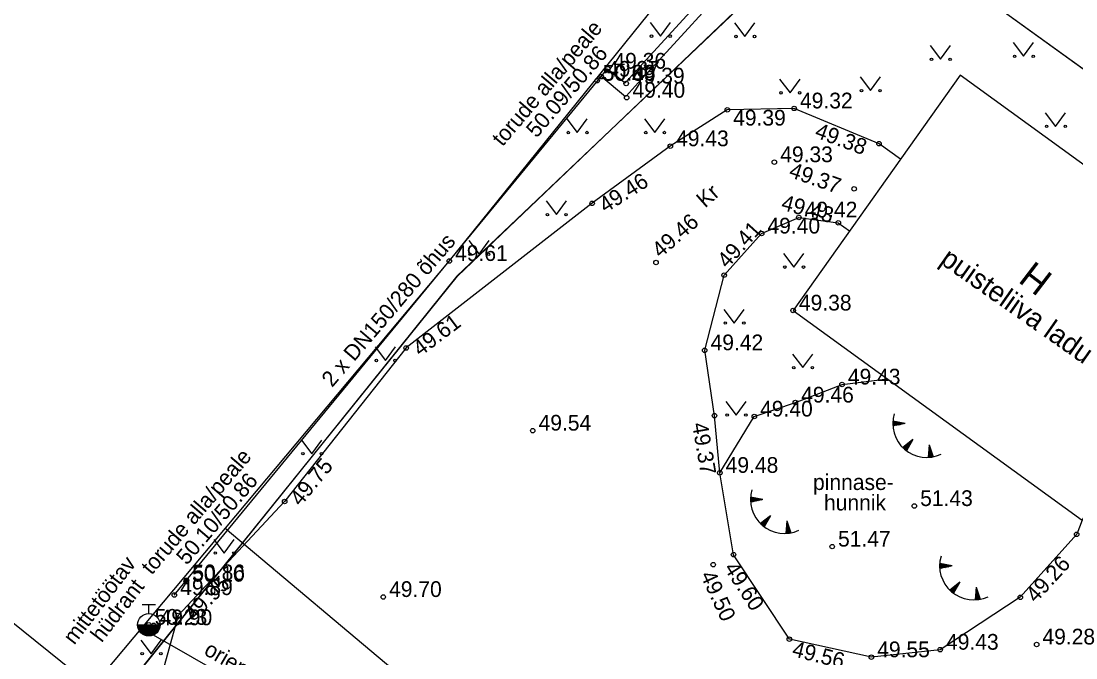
# Model space of a CAD drawing. Extents: x 640876 to 641418, y 6455595 to 6456085.
# Drawn here: x 641120.09 to 641167.04, y 6455852.02 to 6455880.34 of the extents above; entities that cross this region are included whole.
import ezdxf

# ---------------------------------------------------------------- set-up
doc = ezdxf.new("R2010")
doc.units = 0
for name, color, linetype in [('ABIJOONIS', 7, 'Continuous'), ('HALJASTUS', 7, 'Continuous'), ('HOONE', 7, 'Continuous'), ('HOONEDET', 7, 'Continuous'), ('KORGUS', 7, 'Continuous'), ('KTRASS', 7, 'Continuous'), ('MOOTKORG', 7, 'Continuous'), ('MOOTMPUNKT', 7, 'Continuous'), ('PIIR', 7, 'Continuous'), ('RELJEEF', 7, 'Continuous'), ('TEE', 7, 'Continuous'), ('TTRASS', 7, 'Continuous'), ('VKAEV', 7, 'Continuous'), ('VTRASS', 7, 'Continuous')]:
    doc.layers.add(name, color=color, linetype=linetype)

msp = doc.modelspace()

# ---------------------------------------------------------------- linework, layer by layer
at = {"layer": 'HALJASTUS'}
for p, q in [((641148.087, 6455880.275), (641148.55, 6455879.669)), ((641148.55, 6455879.669), (641148.996, 6455880.275)), ((641151.845, 6455880.262), (641152.309, 6455879.656)), ((641152.309, 6455879.656), (641152.754, 6455880.262)), ((641160.55, 6455879.25), (641161.014, 6455878.644)), ((641161.014, 6455878.644), (641161.459, 6455879.25)), ((641164.248, 6455879.383), (641164.711, 6455878.776)), ((641164.711, 6455878.776), (641165.157, 6455879.383)), ((641157.433, 6455877.857), (641157.896, 6455877.25)), ((641157.896, 6455877.25), (641158.342, 6455877.857)), ((641153.852, 6455877.757), (641154.315, 6455877.151)), ((641154.315, 6455877.151), (641154.761, 6455877.757)), ((641144.384, 6455875.991), (641144.848, 6455875.384)), ((641144.848, 6455875.384), (641145.293, 6455875.991)), ((641147.833, 6455875.991), (641148.296, 6455875.384)), ((641148.296, 6455875.384), (641148.742, 6455875.991)), ((641165.673, 6455876.264), (641166.137, 6455875.658)), ((641166.137, 6455875.658), (641166.582, 6455876.264)), ((641143.456, 6455872.341), (641143.919, 6455871.734)), ((641143.919, 6455871.734), (641144.365, 6455872.341)), ((641140.014, 6455870.577), (641140.477, 6455869.971)), ((641140.477, 6455869.971), (641140.923, 6455870.577)), ((641154.023, 6455870.006), (641154.487, 6455869.399)), ((641154.487, 6455869.399), (641154.932, 6455870.006)), ((641151.37, 6455867.517), (641151.834, 6455866.911)), ((641151.834, 6455866.911), (641152.279, 6455867.517)), ((641135.845, 6455865.852), (641136.308, 6455865.245)), ((641136.308, 6455865.245), (641136.754, 6455865.852)), ((641154.419, 6455865.534), (641154.883, 6455864.928)), ((641154.883, 6455864.928), (641155.328, 6455865.534)), ((641151.455, 6455863.426), (641151.919, 6455862.819)), ((641151.919, 6455862.819), (641152.364, 6455863.426)), ((641132.572, 6455861.708), (641133.035, 6455861.101)), ((641133.035, 6455861.101), (641133.481, 6455861.708)), ((641128.672, 6455857.287), (641129.135, 6455856.681)), ((641129.135, 6455856.681), (641129.581, 6455857.287)), ((641125.419, 6455852.811), (641125.882, 6455852.205)), ((641125.882, 6455852.205), (641126.328, 6455852.811))]:
    msp.add_line(p, q, dxfattribs=at)
msp.add_lwpolyline([(641151.191, 6455860.249), (641152.724, 6455862.752), (641154.552, 6455863.375), (641156.629, 6455864.178), (641158.65, 6455864.425)], dxfattribs=at)
for centre in [(641148.149, 6455879.669), (641148.978, 6455879.669), (641151.908, 6455879.656), (641152.737, 6455879.656), (641164.31, 6455878.776), (641165.139, 6455878.776), (641160.613, 6455878.644), (641161.441, 6455878.644), (641153.914, 6455877.151), (641154.743, 6455877.151), (641157.495, 6455877.25), (641158.324, 6455877.25), (641165.736, 6455875.658), (641166.565, 6455875.658), (641144.447, 6455875.384), (641145.275, 6455875.384), (641147.895, 6455875.384), (641148.724, 6455875.384), (641143.518, 6455871.734), (641144.347, 6455871.734), (641140.076, 6455869.971), (641140.905, 6455869.971), (641154.086, 6455869.399), (641154.914, 6455869.399), (641151.433, 6455866.911), (641152.261, 6455866.911), (641135.907, 6455865.245), (641136.736, 6455865.245), (641154.482, 6455864.928), (641155.311, 6455864.928), (641151.518, 6455862.819), (641152.347, 6455862.819), (641132.634, 6455861.101), (641133.463, 6455861.101), (641128.734, 6455856.681), (641129.563, 6455856.681), (641125.481, 6455852.205), (641126.31, 6455852.205)]:
    msp.add_circle(centre, 0.055, dxfattribs=at)
at = {"layer": 'HOONE'}
for points in [[(641167.4, 6455884.521), (641162.961, 6455888.191), (641157.603, 6455892.559), (641139.149, 6455869.673), (641123.276, 6455850.742)], [(641154.452, 6455867.469), (641167.313, 6455858.143), (641174.747, 6455868.605), (641161.886, 6455877.931), (641154.452, 6455867.469)]]:
    msp.add_lwpolyline(points, dxfattribs=at)
at = {"layer": 'HOONEDET'}
msp.add_line((641085.613, 6455880.964), (641123.276, 6455850.742), dxfattribs=at)
at = {"layer": 'KORGUS'}
for centre in [(641151.524, 6455876.394), (641158.276, 6455874.888), (641157.167, 6455872.877), (641145.506, 6455872.238), (641156.465, 6455871.367), (641148.352, 6455869.601), (641151.382, 6455869.04), (641137.229, 6455865.803), (641154.552, 6455863.375), (641150.951, 6455862.79), (641142.864, 6455862.128), (641131.822, 6455858.971), (641159.848, 6455858.773), (641151.802, 6455856.608), (641156.193, 6455856.969), (641150.897, 6455856.167), (641136.211, 6455854.728), (641164.563, 6455854.713), (641127.09, 6455853.908), (641154.287, 6455852.849), (641165.291, 6455852.616)]:
    msp.add_circle(centre, 0.1, dxfattribs=at)
at = {"layer": 'KTRASS'}
msp.add_line((641138.181, 6455850.219), (641129.171, 6455857.773), dxfattribs=at)
at = {"layer": 'MOOTMPUNKT'}
for centre in [(641146.196, 6455878.224), (641145.728, 6455877.689), (641145.914, 6455877.866), (641147.022, 6455877.566), (641147.047, 6455876.932), (641154.5, 6455876.457), (641148.985, 6455874.775), (641153.619, 6455874.066), (641154.71, 6455871.606), (641153.052, 6455870.892), (641139.149, 6455869.673), (641154.452, 6455867.469), (641150.519, 6455865.7), (641156.629, 6455864.178), (641152.724, 6455862.752), (641151.191, 6455860.249), (641167.075, 6455857.516), (641127.44, 6455855.41), (641127.456, 6455855.472), (641126.912, 6455854.813), (641125.776, 6455853.493), (641125.997, 6455853.47), (641160.999, 6455852.383), (641157.935, 6455852.048)]:
    msp.add_circle(centre, 0.1, dxfattribs=at)
at = {"layer": 'PIIR'}
for points in [[(641222.58, 6455998.61), (641237.36, 6455995.24), (641235.34, 6455991.29), (641228.11, 6455971.68), (641220.5, 6455953.19), (641213.41, 6455936.25), (641201.58, 6455908.74), (641224.93, 6455905.88), (641191.87, 6455860.58), (641157.02, 6455885.66), (641160.91, 6455891.99), (641102.26, 6455951.82), (641074.95, 6455979.64), (641084.84, 6455991.92)], [(641098.62, 6455818.85), (641093.41, 6455823.22), (641084.65, 6455830.08), (641067.32, 6455843.61), (641055.55, 6455852.8), (641061.31, 6455859.9), (641051.68, 6455867.61), (641067, 6455888.54), (641060.97, 6455894.57), (641075.14, 6455914.24), (641087.11, 6455930.82), (641102.26, 6455951.82), (641160.91, 6455891.99), (641157.02, 6455885.66), (641139.49, 6455869), (641124.05, 6455849.81)], [(641216.67, 6455752.61), (641192, 6455776.86), (641152.58, 6455788.91), (641136.9, 6455789.33), (641119.28, 6455802.72), (641101.72, 6455816.27), (641098.61, 6455818.83), (641124.03, 6455849.78), (641139.51, 6455868.99), (641157, 6455885.69), (641191.84, 6455860.59), (641168.46, 6455829.03), (641191.37, 6455806.79), (641234.69, 6455771.62)]]:
    msp.add_lwpolyline(points, close=True, dxfattribs=at)
at = {"layer": 'RELJEEF'}
for p, q in [((641158.884, 6455862.455), (641158.984, 6455862.535)), ((641158.885, 6455862.488), (641158.952, 6455862.541)), ((641158.885, 6455862.423), (641159.016, 6455862.529)), ((641158.886, 6455862.521), (641158.919, 6455862.547)), ((641158.886, 6455862.392), (641159.048, 6455862.522)), ((641158.887, 6455862.361), (641159.081, 6455862.516)), ((641159.445, 6455862.446), (641158.888, 6455862.553)), ((641159.445, 6455862.446), (641158.889, 6455862.337)), ((641158.899, 6455862.339), (641159.113, 6455862.51)), ((641158.952, 6455862.349), (641159.145, 6455862.504)), ((641159.005, 6455862.36), (641159.177, 6455862.498)), ((641159.058, 6455862.37), (641159.21, 6455862.491)), ((641159.111, 6455862.38), (641159.242, 6455862.485)), ((641159.164, 6455862.391), (641159.274, 6455862.479)), ((641159.217, 6455862.401), (641159.306, 6455862.473)), ((641159.27, 6455862.412), (641159.338, 6455862.466)), ((641159.323, 6455862.422), (641159.371, 6455862.46)), ((641159.376, 6455862.432), (641159.403, 6455862.454)), ((641159.777, 6455861.726), (641159.332, 6455861.374)), ((641159.356, 6455861.351), (641159.357, 6455861.394)), ((641159.38, 6455861.329), (641159.383, 6455861.414)), ((641159.404, 6455861.307), (641159.409, 6455861.434)), ((641159.429, 6455861.286), (641159.434, 6455861.455)), ((641159.453, 6455861.267), (641159.46, 6455861.475)), ((641159.477, 6455861.248), (641159.486, 6455861.495)), ((641159.777, 6455861.726), (641159.497, 6455861.233)), ((641159.502, 6455861.242), (641159.512, 6455861.516)), ((641159.529, 6455861.289), (641159.537, 6455861.536)), ((641159.555, 6455861.336), (641159.563, 6455861.557)), ((641159.582, 6455861.383), (641159.589, 6455861.577)), ((641159.609, 6455861.43), (641159.615, 6455861.597)), ((641159.635, 6455861.477), (641159.64, 6455861.618)), ((641159.662, 6455861.524), (641159.666, 6455861.638)), ((641159.689, 6455861.571), (641159.692, 6455861.658)), ((641159.715, 6455861.618), (641159.718, 6455861.679)), ((641159.742, 6455861.665), (641159.743, 6455861.699)), ((641160.509, 6455861.502), (641160.466, 6455860.936)), ((641160.58, 6455861.281), (641160.498, 6455861.361)), ((641160.563, 6455861.332), (641160.501, 6455861.394)), ((641160.547, 6455861.384), (641160.503, 6455861.426)), ((641160.53, 6455861.435), (641160.506, 6455861.459)), ((641160.509, 6455861.502), (641160.682, 6455860.962)), ((641160.499, 6455860.938), (641160.469, 6455860.968)), ((641160.532, 6455860.941), (641160.471, 6455861.001)), ((641160.564, 6455860.944), (641160.474, 6455861.034)), ((641160.596, 6455860.948), (641160.476, 6455861.066)), ((641160.627, 6455860.952), (641160.479, 6455861.099)), ((641160.657, 6455860.958), (641160.481, 6455861.132)), ((641160.678, 6455860.972), (641160.484, 6455861.165)), ((641160.662, 6455861.023), (641160.486, 6455861.197)), ((641160.645, 6455861.075), (641160.488, 6455861.23)), ((641160.629, 6455861.126), (641160.491, 6455861.263)), ((641160.613, 6455861.178), (641160.493, 6455861.296)), ((641160.596, 6455861.229), (641160.496, 6455861.328)), ((641152.551, 6455859.103), (641152.618, 6455859.157)), ((641152.551, 6455859.071), (641152.65, 6455859.151)), ((641152.551, 6455859.039), (641152.682, 6455859.144)), ((641152.552, 6455859.136), (641152.586, 6455859.163)), ((641152.552, 6455859.008), (641152.715, 6455859.138)), ((641152.553, 6455858.977), (641152.747, 6455859.132)), ((641153.111, 6455859.062), (641152.554, 6455859.169)), ((641153.111, 6455859.062), (641152.555, 6455858.952)), ((641152.565, 6455858.954), (641152.779, 6455859.126)), ((641152.618, 6455858.965), (641152.811, 6455859.119)), ((641152.671, 6455858.975), (641152.844, 6455859.113)), ((641152.724, 6455858.986), (641152.876, 6455859.107)), ((641152.777, 6455858.996), (641152.908, 6455859.101)), ((641152.83, 6455859.006), (641152.94, 6455859.095)), ((641152.883, 6455859.017), (641152.973, 6455859.088)), ((641152.936, 6455859.027), (641153.005, 6455859.082)), ((641152.989, 6455859.038), (641153.037, 6455859.076)), ((641153.042, 6455859.048), (641153.069, 6455859.07)), ((641153.443, 6455858.341), (641152.999, 6455857.989)), ((641153.095, 6455857.902), (641153.101, 6455858.07)), ((641153.119, 6455857.882), (641153.126, 6455858.091)), ((641153.144, 6455857.863), (641153.152, 6455858.111)), ((641153.443, 6455858.341), (641153.163, 6455857.849)), ((641153.168, 6455857.858), (641153.178, 6455858.132)), ((641153.195, 6455857.905), (641153.204, 6455858.152)), ((641153.222, 6455857.952), (641153.229, 6455858.172)), ((641153.248, 6455857.999), (641153.255, 6455858.193)), ((641153.275, 6455858.046), (641153.281, 6455858.213)), ((641153.302, 6455858.093), (641153.307, 6455858.233)), ((641153.328, 6455858.14), (641153.332, 6455858.254)), ((641153.355, 6455858.187), (641153.358, 6455858.274)), ((641153.382, 6455858.234), (641153.384, 6455858.295)), ((641153.408, 6455858.28), (641153.41, 6455858.315)), ((641154.175, 6455858.117), (641154.133, 6455857.552)), ((641154.197, 6455858.051), (641154.172, 6455858.075)), ((641154.175, 6455858.117), (641154.348, 6455857.578)), ((641153.022, 6455857.967), (641153.024, 6455858.009)), ((641153.046, 6455857.944), (641153.049, 6455858.03)), ((641153.071, 6455857.923), (641153.075, 6455858.05)), ((641154.198, 6455857.557), (641154.138, 6455857.617)), ((641154.231, 6455857.56), (641154.14, 6455857.649)), ((641154.262, 6455857.564), (641154.143, 6455857.682)), ((641154.293, 6455857.568), (641154.145, 6455857.715)), ((641154.324, 6455857.573), (641154.147, 6455857.748)), ((641154.345, 6455857.588), (641154.15, 6455857.78)), ((641154.328, 6455857.639), (641154.152, 6455857.813)), ((641154.312, 6455857.691), (641154.155, 6455857.846)), ((641154.295, 6455857.742), (641154.157, 6455857.879)), ((641154.279, 6455857.793), (641154.16, 6455857.911)), ((641154.262, 6455857.845), (641154.162, 6455857.944)), ((641154.246, 6455857.896), (641154.165, 6455857.977)), ((641154.229, 6455857.948), (641154.167, 6455858.009)), ((641154.213, 6455857.999), (641154.17, 6455858.042)), ((641154.165, 6455857.554), (641154.135, 6455857.584)), ((641160.974, 6455856.15), (641161.041, 6455856.204)), ((641160.974, 6455856.118), (641161.073, 6455856.198)), ((641160.974, 6455856.086), (641161.105, 6455856.191)), ((641160.975, 6455856.183), (641161.009, 6455856.21)), ((641161.534, 6455856.109), (641160.977, 6455856.216)), ((641160.975, 6455856.055), (641161.137, 6455856.185)), ((641160.976, 6455856.024), (641161.17, 6455856.179)), ((641161.534, 6455856.109), (641160.978, 6455855.999)), ((641160.988, 6455856.001), (641161.202, 6455856.173)), ((641161.041, 6455856.012), (641161.234, 6455856.166)), ((641161.094, 6455856.022), (641161.266, 6455856.16)), ((641161.147, 6455856.033), (641161.299, 6455856.154)), ((641161.2, 6455856.043), (641161.331, 6455856.148)), ((641161.253, 6455856.054), (641161.363, 6455856.142)), ((641161.306, 6455856.064), (641161.395, 6455856.135)), ((641161.359, 6455856.074), (641161.428, 6455856.129)), ((641161.412, 6455856.085), (641161.46, 6455856.123)), ((641161.465, 6455856.095), (641161.492, 6455856.117)), ((641161.866, 6455855.388), (641161.421, 6455855.036)), ((641161.866, 6455855.388), (641161.586, 6455854.896)), ((641161.698, 6455855.093), (641161.704, 6455855.26)), ((641161.724, 6455855.14), (641161.729, 6455855.28)), ((641161.751, 6455855.187), (641161.755, 6455855.301)), ((641161.778, 6455855.234), (641161.781, 6455855.321)), ((641161.804, 6455855.281), (641161.807, 6455855.342)), ((641161.831, 6455855.328), (641161.832, 6455855.362)), ((641161.445, 6455855.014), (641161.446, 6455855.056)), ((641161.469, 6455854.991), (641161.472, 6455855.077)), ((641161.493, 6455854.97), (641161.498, 6455855.097)), ((641161.518, 6455854.949), (641161.524, 6455855.117)), ((641161.542, 6455854.929), (641161.549, 6455855.138)), ((641161.566, 6455854.91), (641161.575, 6455855.158)), ((641161.591, 6455854.905), (641161.601, 6455855.179)), ((641161.618, 6455854.952), (641161.627, 6455855.199)), ((641161.644, 6455854.999), (641161.652, 6455855.219)), ((641161.671, 6455855.046), (641161.678, 6455855.24)), ((641162.598, 6455855.164), (641162.556, 6455854.599)), ((641162.747, 6455854.62), (641162.57, 6455854.795)), ((641162.768, 6455854.635), (641162.573, 6455854.827)), ((641162.751, 6455854.686), (641162.575, 6455854.86)), ((641162.735, 6455854.738), (641162.578, 6455854.893)), ((641162.718, 6455854.789), (641162.58, 6455854.926)), ((641162.702, 6455854.84), (641162.583, 6455854.958)), ((641162.685, 6455854.892), (641162.585, 6455854.991)), ((641162.669, 6455854.943), (641162.587, 6455855.024)), ((641162.652, 6455854.995), (641162.59, 6455855.057)), ((641162.636, 6455855.046), (641162.592, 6455855.089)), ((641162.619, 6455855.098), (641162.595, 6455855.122)), ((641162.598, 6455855.164), (641162.771, 6455854.625)), ((641162.588, 6455854.601), (641162.558, 6455854.631)), ((641162.621, 6455854.604), (641162.56, 6455854.664)), ((641162.653, 6455854.607), (641162.563, 6455854.696)), ((641162.685, 6455854.611), (641162.565, 6455854.729)), ((641162.716, 6455854.615), (641162.568, 6455854.762))]:
    msp.add_line(p, q, dxfattribs=at)
for centre in [(641160.398, 6455862.448), (641154.064, 6455859.064), (641162.487, 6455856.111)]:
    msp.add_arc(centre, 1.514, 163.4234, 295.1745, dxfattribs=at)
at = {"layer": 'TEE'}
for points in [[(641159.238, 6455874.204), (641158.276, 6455874.888), (641154.5, 6455876.457), (641151.524, 6455876.394), (641148.985, 6455874.775), (641145.506, 6455872.238), (641137.229, 6455865.803), (641131.822, 6455858.971), (641127.09, 6455853.908), (641125.918, 6455849.675), (641127.928, 6455844.823), (641130.752, 6455841.149), (641137.584, 6455833.839), (641144.779, 6455828.121), (641152.823, 6455822.069), (641161.624, 6455813.864), (641167.235, 6455809.577)], [(641167.313, 6455858.143), (641167.075, 6455857.516), (641164.563, 6455854.713), (641160.999, 6455852.383), (641157.935, 6455852.048), (641154.287, 6455852.849), (641151.802, 6455856.608), (641151.191, 6455860.249), (641150.951, 6455862.79), (641150.519, 6455865.7), (641151.382, 6455869.04), (641153.052, 6455870.892), (641154.71, 6455871.606), (641156.465, 6455871.367), (641156.968, 6455871.01)]]:
    msp.add_lwpolyline(points, dxfattribs=at)
at = {"layer": 'TTRASS'}
msp.add_line((641146.994, 6455876.975), (641145.906, 6455877.872), dxfattribs=at)
for points in [[(641146.983, 6455877.597), (641147.637, 6455878.312), (641148.076, 6455878.791), (641148.587, 6455879.349), (641156.827, 6455888.351), (641157.502, 6455889.088), (641158.299, 6455888.492), (641167.659, 6455881.582), (641177.2, 6455874.303), (641186.795, 6455867.097), (641195.745, 6455860.541), (641196.509, 6455859.853), (641197.119, 6455860.535), (641205.5, 6455869.137), (641213.939, 6455877.707), (641222.42, 6455886.169), (641230.878, 6455894.702), (641235.947, 6455899.687), (641236.146, 6455899.925), (641236.328, 6455899.987), (641239.542, 6455899.756)], [(641240.141, 6455899.285), (641236.489, 6455899.529), (641236.348, 6455899.464), (641230.948, 6455894.114), (641222.434, 6455885.667), (641213.976, 6455877.157), (641205.539, 6455868.624), (641197.23, 6455859.957), (641196.541, 6455859.328), (641186.928, 6455866.582), (641177.306, 6455873.752), (641167.696, 6455880.94), (641158.359, 6455887.923), (641157.562, 6455888.52), (641156.887, 6455887.782), (641148.647, 6455878.781), (641148.136, 6455878.223), (641147.697, 6455877.743), (641147.022, 6455877.006)], [(641126.912, 6455854.813), (641146.196, 6455878.224), (641146.983, 6455877.597)]]:
    msp.add_lwpolyline(points, dxfattribs=at)
at = {"layer": 'VKAEV'}
for p, q in [((641125.476, 6455854.393), (641126.076, 6455854.393)), ((641125.776, 6455853.993), (641125.776, 6455854.393)), ((641125.276, 6455853.493), (641126.276, 6455853.493))]:
    msp.add_line(p, q, dxfattribs=at)
msp.add_circle((641125.776, 6455853.493), 0.5, dxfattribs=at)
for radius in [0.475, 0.45, 0.425, 0.4, 0.375, 0.35, 0.325, 0.3, 0.275, 0.25, 0.225, 0.2, 0.175, 0.15, 0.125, 0.1, 0.075, 0.05]:
    msp.add_arc((641125.776, 6455853.493), radius, 180, 0, dxfattribs=at)
at = {"layer": 'VTRASS'}
msp.add_lwpolyline([(641125.449, 6455853.334), (641132.318, 6455849.405), (641171.673, 6455826.892)], dxfattribs=at)

# ---------------------------------------------------------------- texts
at = {"layer": 'ABIJOONIS'}
for s, p in [('mittetöötav', (641122.458, 6455852.566)), ('hüdrant', (641123.681, 6455852.666))]:
    msp.add_text(s, height=0.7, rotation=52.5524, dxfattribs=at).set_placement(p)
at = {"layer": 'HALJASTUS'}
for s, p in [('pinnase-', (641155.339, 6455859.486)), ('hunnik', (641155.829, 6455858.576))]:
    msp.add_text(s, height=0.7, dxfattribs=at).set_placement(p)
at = {"layer": 'HOONE'}
for s, height, rotation, p in [('puisteliiva ladu', 0.9, 324.9053, (641160.939, 6455869.595)), ('H', 1.2, 142.5447, (641166.075, 6455869.013))]:
    msp.add_text(s, height=height, rotation=rotation, dxfattribs=at).set_placement(p)
at = {"layer": 'KORGUS'}
for s, p in [(' 49.39', (641151.524, 6455875.694)), (' 49.46', (641154.552, 6455863.375)), (' 49.54', (641142.864, 6455862.128)), (' 51.43', (641159.848, 6455858.773)), (' 51.47', (641156.193, 6455856.969)), (' 49.70', (641136.211, 6455854.728)), (' 49.28', (641165.291, 6455852.616))]:
    msp.add_text(s, height=0.7, dxfattribs=at).set_placement(p)
for s, rotation, p in [(' 49.38', 339.701, (641155.129, 6455875.277)), (' 49.46', 32.4122, (641145.881, 6455871.647)), (' 49.37', 340.7416, (641153.977, 6455873.509)), (' 49.43', 344.799, (641153.632, 6455872.031)), (' 49.46', 41.2439, (641148.352, 6455869.601)), (' 49.41', 47.9397, (641151.349, 6455869.114)), (' 49.61', 36.9386, (641137.65, 6455865.244)), (' 49.37', 279.6785, (641149.909, 6455862.685)), (' 49.75', 50.4693, (641132.362, 6455858.525)), (' 49.26', 47.4909, (641165.079, 6455854.24)), (' 49.50', 294.8176, (641150.201, 6455855.935)), (' 49.60', 302.7281, (641151.213, 6455856.23)), (' 49.95', 44.7134, (641127.582, 6455853.411)), (' 49.56', 345.779, (641154.115, 6455852.17))]:
    msp.add_text(s, height=0.7, rotation=rotation, dxfattribs=at).set_placement(p)
at = {"layer": 'MOOTKORG'}
for s, p in [(' 49.36', (641146.196, 6455878.224)), (' 50.09', (641145.715, 6455877.694)), (' 50.86', (641145.728, 6455877.689)), (' 49.37', (641145.914, 6455877.866)), (' 49.39', (641147.022, 6455877.566)), (' 49.40', (641147.047, 6455876.932)), (' 49.32', (641154.5, 6455876.457)), (' 49.43', (641148.985, 6455874.775)), (' 49.33', (641153.619, 6455874.066)), (' 49.42', (641154.71, 6455871.606)), (' 49.40', (641153.052, 6455870.892)), (' 49.61', (641139.149, 6455869.673)), (' 49.38', (641154.452, 6455867.469)), (' 49.42', (641150.519, 6455865.7)), (' 49.43', (641156.629, 6455864.178)), (' 49.40', (641152.724, 6455862.752)), (' 49.48', (641151.191, 6455860.249)), (' 50.10', (641127.44, 6455855.41)), (' 50.86', (641127.456, 6455855.472)), (' 49.89', (641126.912, 6455854.813)), (' 50.23', (641125.776, 6455853.493)), (' 49.90', (641125.997, 6455853.47)), (' 49.43', (641160.999, 6455852.383)), (' 49.55', (641157.935, 6455852.048))]:
    msp.add_text(s, height=0.7, dxfattribs=at).set_placement(p)
at = {"layer": 'TEE'}
msp.add_text('Kr', height=0.7, rotation=41.4262, dxfattribs=at).set_placement((641150.532, 6455872.004))
at = {"layer": 'TTRASS'}
for s, p in [('torude alla/peale', (641141.516, 6455874.729)), ('50.09/50.86', (641143.037, 6455875.111)), ('2 x DN150/280 õhus', (641133.936, 6455864.022)), ('torude alla/peale', (641125.901, 6455855.675)), ('50.10/50.86', (641127.467, 6455856.11))]:
    msp.add_text(s, height=0.7, rotation=49.5618, dxfattribs=at).set_placement(p)
at = {"layer": 'VTRASS'}
msp.add_text('orient', height=0.7, rotation=329.7779, dxfattribs=at).set_placement((641128.182, 6455852.199))

doc.saveas('drawing.dxf')
